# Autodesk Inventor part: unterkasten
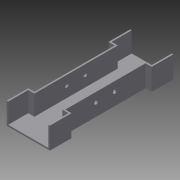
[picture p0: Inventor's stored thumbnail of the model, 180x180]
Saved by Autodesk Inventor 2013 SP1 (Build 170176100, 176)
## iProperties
Created: 2012-11
Part Number: unterkasten
Material: Allgemein
Document SubType Name: Modeling
Designer: macuser
Density: 1 g/cm^3
Author: macuser
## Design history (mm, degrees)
sketch "Skizze1"
  geometry: L1 (0, -56)-(0, 56) reference; L2 (-280, 0)-(280, 0) reference; L3 (-200, 40)-(200, 40); L4 (200, 40)-(200, -40); L5 (200, -40)-(-200, -40); L6 (-200, -40)-(-200, 40); 1 further point
  constraints: 8 end point, 2 parallel, 1 horizontal, 1 perpendicular, 2 other
  dimensions: "d0" = 400 distance of L4.end L5.end; "d1" = 80 distance of L3.end L4.end
extrude "Extrusion1" new body sketch "Skizze1" distance "d2" = 100; taper "d3" = 0 deg
feature "Wandstärke1" dims "d4" = 5
sketch "Skizze2"
  geometry: L1 (-40, 200)-(-40, -200) reference; L2 (-40, -200)-(40, -200) reference; L3 (40, 200)-(-40, 200) reference; L4 (0, -200)-(0, 200); L5 (0, 0)-(0, -30); L6 (0, -30)-(-40, -30); L7 (0, 0)-(0, 30); L8 (0, 30)-(-40, 30)
  constraints: 10 end point, 4 point on line, 2 midpoint, 2 perpendicular
  dimensions: "d5" = 30 distance of L5.start L5.end; "d6" = 30 distance of L5.start L7.end
hole "Bohrung1" sketch "Skizze2" at (0, -30), (0, 30) diameter "d7" = 12; stored, may be unused: countersink angle "d11" = 90 deg, drill point angle "d13" = 118 deg; dims "d8" = 6, "d9" = 4, "d10" = 2, "d12" = 8
sketch "Skizze3"
  geometry: L1 (-40, 200)-(-40, -200) reference; L2 (-40, -200)-(40, -200) reference; L3 (40, 200)-(-40, 200) reference; L4 (0, -280)-(0, 280) reference; L5 (56, 0)-(-56, 0) reference; L6 (-40, 200)-(-40, -200); L7 (0, 200)-(0, -200); L8 (-30, 200)-(-30, -200); 1 further point
  constraints: 6 end point, 4 point on line, 2 midpoint, 1 collinear, 1 perpendicular
  dimensions: "d14" = 10 distance between parallel lines of L6 L8
extrude "Extrusion2" cut sketch "Skizze3" distance "d15" = 100; taper "d16" = 0 deg
sketch "Skizze4"
  geometry: L1 (40, -200)-(40, 200) reference; L2 (-30, 200)-(40, 200); L3 (40, 200)-(40, 130); L4 (40, 130)-(-30, 130); L5 (-30, 130)-(-30, 200); L6 (-30, -200)-(40, -200); L7 (40, -200)-(40, -130); L8 (40, -130)-(-30, -130); L9 (-30, -130)-(-30, -200); 1 further point
  constraints: 16 end point, 4 parallel, 2 horizontal, 2 perpendicular, 1 point on line
  dimensions: "d17" = 70 distance of L2.end L3.end; "d18" = 70 distance of L8.end L7.end; "d19" = 70 distance of L7.end L6.end
extrude "Extrusion3" join sketch "Skizze4" distance "d20" = 20; taper "d21" = 0 deg
sketch "Skizze5"
  geometry: L1 (0, 0)-(0, 400) reference; L2 (65, 0)-(0, 0); L3 (0, 0)-(0, 65); L4 (0, 65)-(65, 65); L5 (65, 65)-(65, 0); L6 (65, 400)-(0, 400); L7 (0, 400)-(0, 335); L8 (0, 335)-(65, 335); L9 (65, 335)-(65, 400); 1 further point
  constraints: 16 end point, 4 parallel, 2 horizontal, 2 perpendicular, 2 point on line
  dimensions: "d22" = 65 distance of L2.end L3.end; "d23" = 65 distance of L7.end L6.end
extrude "Extrusion4" cut sketch "Skizze5" distance "d24" = 20; taper "d25" = 0 deg
sketch "Skizze6"
  geometry: L1 (30, -200)-(30, 200) reference; L2 (-40, 200)-(30, 200); L3 (30, 200)-(30, 130); L4 (30, 130)-(-40, 130); L5 (-40, 130)-(-40, 200); L6 (-40, -200)-(30, -200); L7 (30, -200)-(30, -130); L8 (30, -130)-(-40, -130); L9 (-40, -130)-(-40, -200); 1 further point
  constraints: 16 end point, 4 parallel, 2 horizontal, 2 perpendicular, 2 point on line
  dimensions: "d26" = 70 distance of L2.end L3.end; "d27" = 70 distance of L7.end L6.end
extrude "Extrusion5" join sketch "Skizze6" distance "d28" = 20; taper "d29" = 0 deg
sketch "Skizze7"
  geometry: L1 (0, 400)-(0, 0) reference; L2 (-65, 400)-(0, 400); L3 (0, 400)-(0, 335); L4 (0, 335)-(-65, 335); L5 (-65, 335)-(-65, 400); L6 (-65, 0)-(0, 0); L7 (0, 0)-(0, 65); L8 (0, 65)-(-65, 65); L9 (-65, 65)-(-65, 0); 1 further point
  constraints: 16 end point, 4 parallel, 2 horizontal, 2 perpendicular, 2 point on line
  dimensions: "d30" = 65 distance of L2.end L3.end; "d31" = 65 distance of L7.end L6.end
extrude "Extrusion6" cut sketch "Skizze7" distance "d32" = 20; taper "d33" = 0 deg
node "Volumenkörper1"
